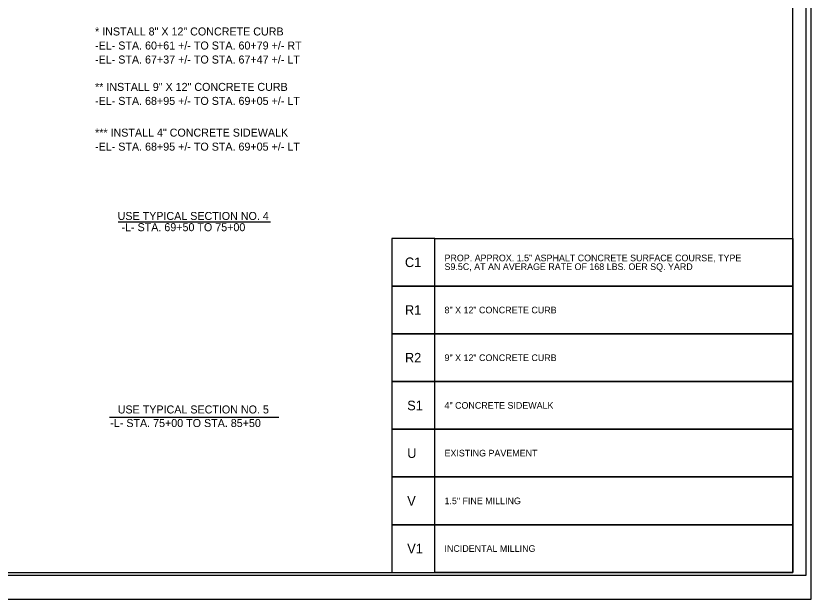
# Model space of a CAD drawing. Extents: x 1022283 to 1026986, y 174822 to 180471.
# Drawn here: x 1024632 to 1026493, y 177721 to 179087 of the extents above; entities that cross this region are included whole.
import ezdxf

# ---------------------------------------------------------------- set-up
doc = ezdxf.new("R2010")
doc.units = 0
for name, color, linetype in [('Prop Dimension', 7, 'Continuous'), ('Prop Pavement Schedule Description CELL', 7, 'Continuous'), ('Sheet Cutting Line CELL', 7, 'Continuous'), ('Sheet Plot Border Inside CELL', 7, 'Continuous'), ('Sheet Plot Border Outside CELL', 7, 'Continuous'), ('Sheet Typical CELL', 7, 'Continuous'), ('Typical Text Label CELL', 7, 'Continuous')]:
    doc.layers.add(name, color=color, linetype=linetype)

msp = doc.modelspace()

# ---------------------------------------------------------------- linework, layer by layer
at = {"layer": 'Prop Pavement Schedule Description CELL'}
for points in [[(1025612.6, 178566.2), (1026450.7, 178566.2), (1026450.7, 178454.5), (1025612.6, 178454.5), (1025612.6, 178566.2), (1025512, 178566.2), (1025512, 178454.5), (1025612.6, 178454.5)], [(1025612.6, 178454.5), (1026450.7, 178454.5), (1026450.7, 178342.7), (1025612.6, 178342.7), (1025612.6, 178454.5), (1025512, 178454.5), (1025512, 178342.7), (1025612.6, 178342.7)], [(1025612.6, 178342.7), (1026450.7, 178342.7), (1026450.7, 178231), (1025612.6, 178231), (1025612.6, 178342.7), (1025512, 178342.7), (1025512, 178231), (1025612.6, 178231)], [(1025612.6, 178231), (1026450.7, 178231), (1026450.7, 178119.2), (1025612.6, 178119.2), (1025612.6, 178231), (1025512, 178231), (1025512, 178119.2), (1025612.6, 178119.2)], [(1025612.6, 178119.2), (1026450.7, 178119.2), (1026450.7, 178007.5), (1025612.6, 178007.5), (1025612.6, 178119.2), (1025512, 178119.2), (1025512, 178007.5), (1025612.6, 178007.5)], [(1025612.6, 178007.5), (1026450.7, 178007.5), (1026450.7, 177895.7), (1025612.6, 177895.7), (1025612.6, 178007.5), (1025512, 178007.5), (1025512, 177895.7), (1025612.6, 177895.7)], [(1025612.6, 177895.7), (1026450.7, 177895.7), (1026450.7, 177784), (1025612.6, 177784), (1025612.6, 177895.7), (1025512, 177895.7), (1025512, 177784), (1025612.6, 177784)]]:
    msp.add_lwpolyline(points, dxfattribs=at)
at = {"layer": 'Sheet Cutting Line CELL'}
msp.add_line((1022283.2, 177721.5), (1026493.2, 177721.5), dxfattribs=at)
at = {"layer": 'Sheet Plot Border Inside CELL'}
msp.add_lwpolyline([(1026482, 180415.4), (1022315.7, 180415.4), (1022315.7, 177777.6), (1026482, 177777.6)], close=True, dxfattribs=at)
at = {"layer": 'Sheet Plot Border Outside CELL'}
msp.add_lwpolyline([(1026493.2, 180471.5), (1022283.2, 180471.5), (1022283.2, 177721.5), (1026493.2, 177721.5)], close=True, dxfattribs=at)
at = {"layer": 'Sheet Typical CELL'}
msp.add_lwpolyline([(1026450.7, 180409), (1022700.7, 180409), (1022700.7, 177784), (1026450.7, 177784)], close=True, dxfattribs=at)
at = {"layer": 'Typical Text Label CELL'}
for p, q in [((1024870.8, 178604.9), (1025227.8, 178604.9)), ((1024850.5, 178147.8), (1025247, 178147.8))]:
    msp.add_line(p, q, dxfattribs=at)

# ---------------------------------------------------------------- texts
at = {"layer": 'Prop Dimension'}
for s, p in [('* INSTALL 8" X 12" CONCRETE CURB ', (1024816.9, 179041.6)), ('-EL- STA. 60+61 +/- TO STA. 60+79 +/- RT', (1024816.9, 179008.7)), ('-EL- STA. 67+37 +/- TO STA. 67+47 +/- LT', (1024816.9, 178975.9)), ('** INSTALL 9" X 12" CONCRETE CURB ', (1024816.9, 178911.8)), ('-EL- STA. 68+95 +/- TO STA. 69+05 +/- LT', (1024816.9, 178879)), ('*** INSTALL 4" CONCRETE SIDEWALK ', (1024816.9, 178804.7)), ('-EL- STA. 68+95 +/- TO STA. 69+05 +/- LT', (1024816.9, 178771.9)), ('-L- STA. 69+50 TO 75+00', (1024878.8, 178583.2)), ('-L- STA. 75+00 TO STA. 85+50', (1024852.5, 178124.5))]:
    msp.add_text(s, height=18.75, dxfattribs=at).set_placement(p)
at = {"layer": 'Prop Pavement Schedule Description CELL'}
for s, height, p in [('C1', 22.35, (1025542.4, 178499.2)), ('PROP. APPROX. 1.5" ASPHALT CONCRETE SURFACE COURSE, TYPE ', 15.576, (1025635, 178512.8)), ('S9.5C, AT AN AVERAGE RATE OF 168 LBS. OER SQ. YARD', 15.576, (1025635, 178492.3)), ('R1', 22.35, (1025542.4, 178387.4)), ('8" X 12" CONCRETE CURB', 15.576, (1025635, 178390.8)), ('R2', 22.35, (1025542.4, 178275.7)), ('9" X 12" CONCRETE CURB', 15.576, (1025635, 178279)), ('S1', 22.35, (1025547.7, 178163.9)), ('4" CONCRETE SIDEWALK', 15.576, (1025635, 178167.3)), ('U', 22.3, (1025547.7, 178052.2)), ('EXISTING PAVEMENT', 15.576, (1025635, 178055.6)), ('V', 22.3, (1025547.7, 177940.4)), ('1.5" FINE MILLING', 15.576, (1025635, 177943.8)), ('V1', 22.35, (1025547.7, 177828.7)), ('INCIDENTAL MILLING', 15.576, (1025635, 177832.1))]:
    msp.add_text(s, height=height, dxfattribs=at).set_placement(p)
at = {"layer": 'Typical Text Label CELL'}
for s, p in [('USE TYPICAL SECTION NO. 4', (1024869.7, 178609.5)), ('USE TYPICAL SECTION NO. 5', (1024870, 178156.3))]:
    msp.add_text(s, height=18.75, dxfattribs=at).set_placement(p)

doc.saveas('drawing.dxf')
